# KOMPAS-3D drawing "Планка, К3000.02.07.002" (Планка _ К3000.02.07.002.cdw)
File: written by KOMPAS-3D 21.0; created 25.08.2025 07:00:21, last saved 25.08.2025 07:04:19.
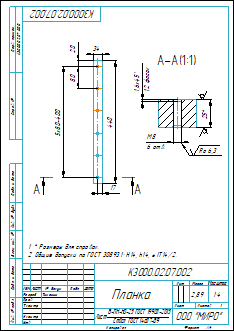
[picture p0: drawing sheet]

Sheet 1: A4, portrait

Document properties: Автор: Lutik; Полное имя файла: C:\Users\Lutik\Yandex.Disk\Документы\Новая папка\Бабка задняя\2D\Плита_К3000.02.07.000\Планка _ К3000.02.07.002.cdw; Масса: 2.891955

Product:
- Part/product: Планка  | designation К3000.02.07.002
    Материал: Лист$dБ-ПН-НО-25 ГОСТ 19903-2015;Ст3сп ГОСТ 14637-89$ (density 7850 kg/m3)
    Масса: 2.891955

Title block, sheet 1: Наименование: Планка; designation: К3000.02.07.002; Материал: Лист Б-ПН-НО-25 ГОСТ 19903-2015 Ст3сп ГОСТ 14637-89; Масса: 2,89; Количество листов документа: 1; organisation: ООО "МИРО"; Форматы листов документа: A4; Разработал: Тимонин

Views: Вид 1, Слева, Разрез 2, Разрез А-А
Referenced files in C:\Users\Lutik\Yandex.Disk\Документы\Новая папка\Бабка задняя\3D\: Планка.m3d
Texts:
  Ra 6,3
  К3000.02.07.002 Планка
Dimensions and other numbers on the sheet: 34; 20; 80; 5х80=; 400; 440; 17; 8; 6 отв.; 25; 1,6; 12 фасок; 1:4; 1; 2,89

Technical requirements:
  * Размеры для справок.
  Общие допуски по ГОСТ 30893.1: Н14, h14, ± IT14/2.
